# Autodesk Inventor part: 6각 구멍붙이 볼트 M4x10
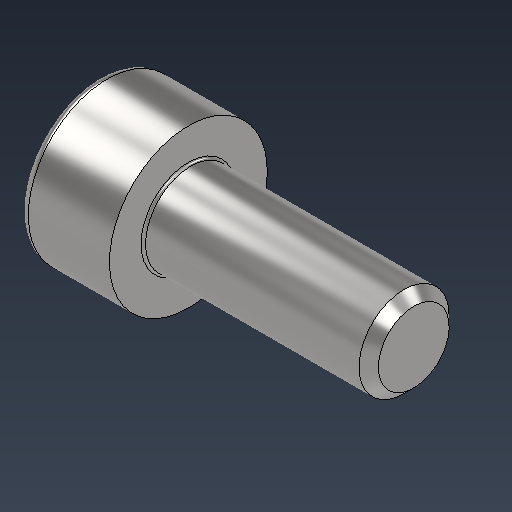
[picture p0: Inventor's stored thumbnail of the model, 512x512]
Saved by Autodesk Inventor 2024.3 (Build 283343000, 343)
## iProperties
Created: 2025-07
Part Number: 6각 구멍붙이 볼트 M4x10
Material: 강철, 연강
Description: 6각머리 태핑 나사
Document SubType Name: Modeling
Designer: user
Density: 7.85 g/cm^3
Appearance: 기본값
Sending System: Autodesk Inventor 2026
Preprocessor: ST-DEVELOPER v20.1
Author: jhkim
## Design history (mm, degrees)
feature "Solid1"
node "솔리드1"
